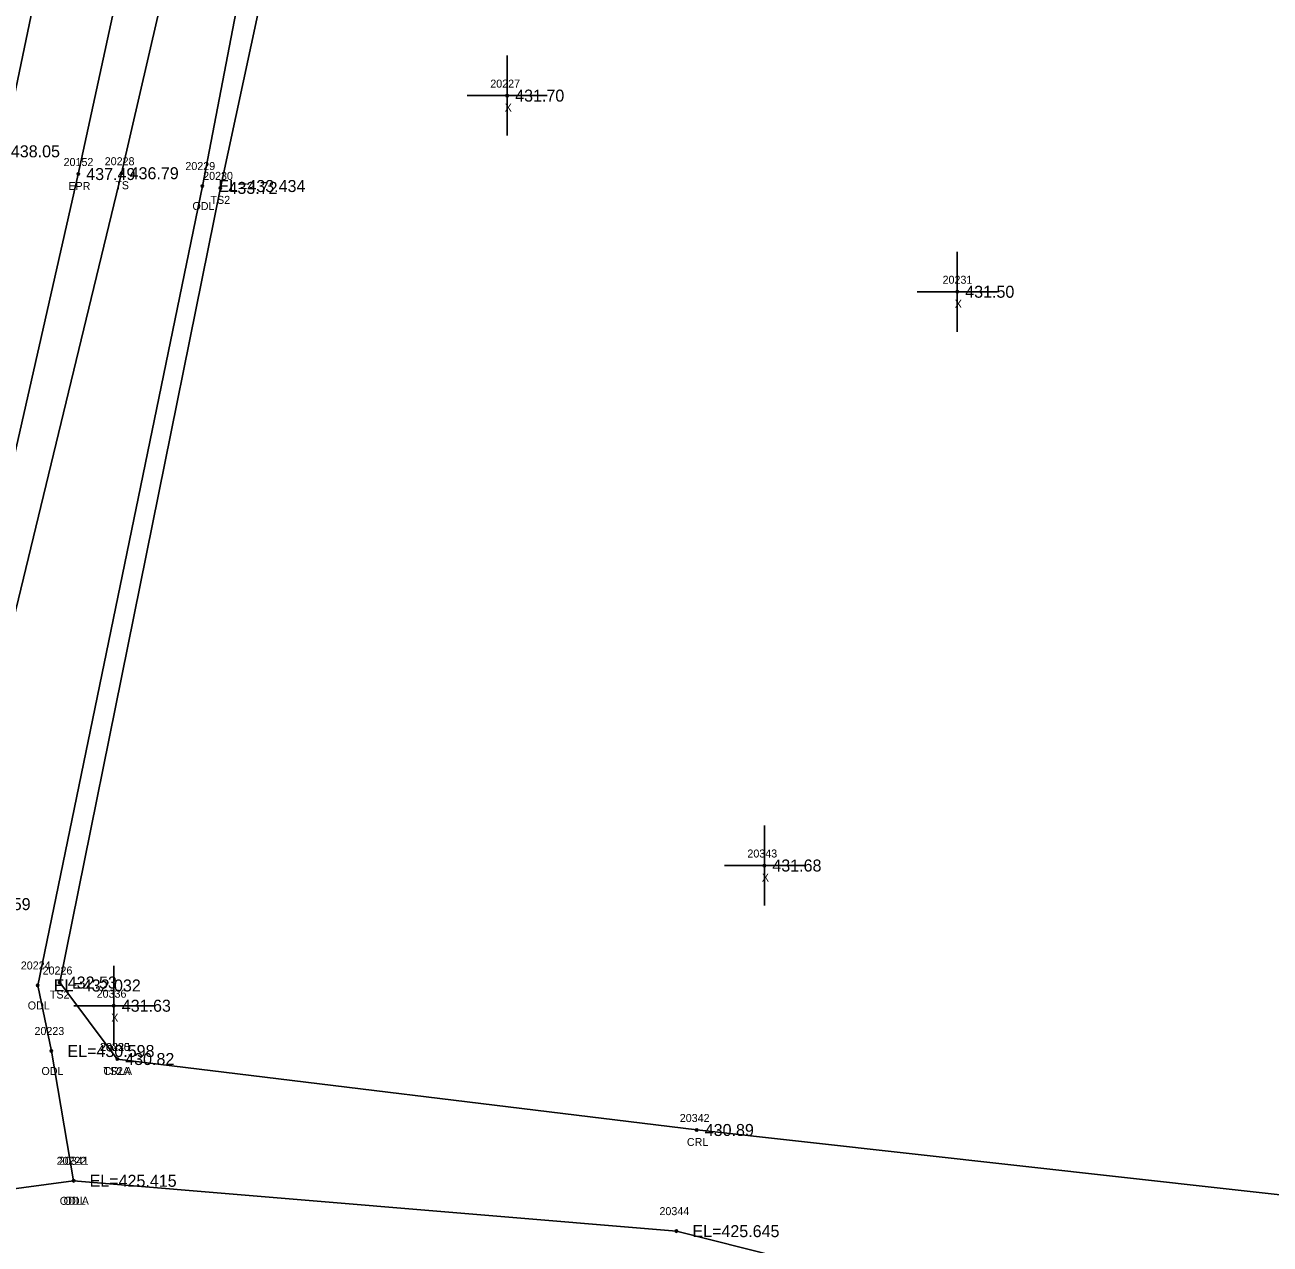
# Model space of a CAD drawing. Extents: x 1755707 to 1756750, y 975854 to 977363.
# Drawn here: x 1756236.1 to 1756391.7, y 976608 to 976760.4 of the extents above; entities that cross this region are included whole.
import ezdxf

# ---------------------------------------------------------------- set-up
doc = ezdxf.new("R2010")
doc.units = 0
for name, color, linetype in [('RD_DTM_BkLn1', 7, 'Continuous'), ('RD_DTM_BkLn2', 7, 'Continuous'), ('RD_DTM_BkLn_txCode', 7, 'Continuous'), ('RD_EX_H2O', 7, 'Continuous'), ('RD_EX_H2O_txCode', 7, 'Continuous'), ('RD_EX_Misc', 7, 'Continuous'), ('RD_EX_Misc_txCode', 7, 'Continuous'), ('RD_EX_Road', 7, 'Continuous'), ('RD_EX_Road_txCode', 7, 'Continuous'), ('RD_EX_TX_H2O_ELEV', 7, 'Continuous'), ('RD_EX_TX_Misc_ELEV', 7, 'Continuous'), ('RD_EX_TX_Road_ELEV', 7, 'Continuous'), ('RD_HC_Survey_ELEV', 7, 'Continuous'), ('RD_SMD_Locator', 7, 'Continuous')]:
    doc.layers.add(name, color=color, linetype=linetype)

msp = doc.modelspace()

# ---------------------------------------------------------------- linework, layer by layer
at = {"layer": 'RD_DTM_BkLn1'}
msp.add_lwpolyline([(1756212.24, 976646.92), (1756233.31, 976744.58), (1756253.87, 976843.36), (1756274.18, 976942.87), (1756294.7, 977044.28), (1756314.7, 977141.54), (1756335.65, 977241.96), (1756357.9, 977342.03)], dxfattribs=at)
at = {"layer": 'RD_DTM_BkLn2'}
for points in [[(1756228.43, 976635.42), (1756229.64, 976650.51), (1756228.61, 976661.27), (1756248.15, 976741.84), (1756270.72, 976839.45), (1756280.12, 976897.48), (1756286.17, 976899.18), (1756290.15, 976895.42)], [(1756247.6, 976631.15), (1756240.42, 976640.71), (1756260.5, 976740.01), (1756281.57, 976838.1), (1756290.15, 976895.42)]]:
    msp.add_lwpolyline(points, dxfattribs=at)
at = {"layer": 'RD_EX_H2O'}
for points in [[(1756242.15, 976615.93), (1756239.38, 976632.15), (1756237.67, 976640.34), (1756258.24, 976740.24), (1756277.14, 976838.38), (1756286.35, 976895.13)], [(1756247.6, 976631.15), (1756320.02, 976622.28), (1756426.93, 976610.4), (1756522.42, 976596.33), (1756612.51, 976536.45), (1756713.08, 976499.13)], [(1755742.06, 976428.66), (1755806.09, 976451.93), (1755887.6, 976439.2), (1755982.53, 976463.01), (1756033.69, 976542.66), (1756128.83, 976549.6), (1756169.54, 976582.49), (1756188.08, 976603.54), (1756206.03, 976613.84), (1756222.85, 976613.36), (1756242.15, 976615.93), (1756317.48, 976609.64), (1756394.89, 976590.11), (1756422.33, 976593.66), (1756518.23, 976582.93), (1756609.24, 976524.24), (1756704.51, 976490.62)]]:
    msp.add_lwpolyline(points, dxfattribs=at)
at = {"layer": 'RD_EX_Misc'}
for p, q in [((1756296.33, 976746.54), (1756296.33, 976756.54)), ((1756291.33, 976751.54), (1756301.33, 976751.54)), ((1756352.57, 976722.03), (1756352.57, 976732.03)), ((1756347.57, 976727.03), (1756357.57, 976727.03)), ((1756328.47, 976650.33), (1756328.47, 976660.33)), ((1756323.47, 976655.33), (1756333.47, 976655.33)), ((1756247.17, 976632.81), (1756247.17, 976642.81)), ((1756242.17, 976637.81), (1756252.17, 976637.81))]:
    msp.add_line(p, q, dxfattribs=at)
at = {"layer": 'RD_EX_Road'}
msp.add_lwpolyline([(1756212.24, 976646.92), (1756220.86, 976645.39), (1756242.73, 976741.74), (1756264.15, 976840.28), (1756284.31, 976940.54), (1756305.17, 977042.39), (1756325.03, 977140.07), (1756346.16, 977239.41), (1756368.47, 977341.2)], dxfattribs=at)
at = {"layer": 'RD_SMD_Locator'}
for centre in [(1756296.33, 976751.54), (1756242.73, 976741.74), (1756248.15, 976741.84), (1756258.24, 976740.24), (1756260.5, 976740.01), (1756352.57, 976727.03), (1756328.47, 976655.33), (1756237.67, 976640.34), (1756240.42, 976640.71), (1756247.17, 976637.81), (1756239.38, 976632.15), (1756247.6, 976631.15), (1756247.6, 976631.15), (1756320.02, 976622.28), (1756242.15, 976615.93), (1756242.15, 976615.93), (1756317.48, 976609.64)]:
    msp.add_circle(centre, 0.15, dxfattribs=at)

# ---------------------------------------------------------------- texts
at = {"layer": 'RD_DTM_BkLn_txCode'}
for s, p in [('20228', (1756246.04, 976742.84)), ('20230', (1756258.34, 976741.01)), ('TS', (1756247.36, 976739.84)), ('TS2', (1756259.26, 976738.01)), ('20226', (1756238.28, 976641.71)), ('TS2', (1756239.18, 976638.71)), ('20225', (1756245.48, 976632.15)), ('TS2A', (1756245.86, 976629.15))]:
    msp.add_text(s, height=1, dxfattribs=at).set_placement(p)
at = {"layer": 'RD_EX_H2O_txCode'}
for s, p in [('20229', (1756256.12, 976742.24)), ('ODL', (1756257, 976737.24)), ('20224', (1756235.55, 976642.34)), ('ODL', (1756236.42, 976637.34)), ('20223', (1756237.26, 976634.15)), ('20330', (1756245.44, 976632.15)), ('ODL', (1756238.13, 976629.15)), ('CRLA', (1756245.88, 976629.15)), ('20342', (1756317.9, 976623.28)), ('CRL', (1756318.79, 976620.28)), ('20222', (1756240.03, 976617.93)), ('20341', (1756240.31, 976617.93)), ('ODLA', (1756240.42, 976612.93)), ('ODL', (1756240.9, 976612.93)), ('20344', (1756315.36, 976611.64))]:
    msp.add_text(s, height=1, dxfattribs=at).set_placement(p)
at = {"layer": 'RD_EX_Misc_txCode'}
for s, p in [('20227', (1756294.22, 976752.54)), ('X', (1756296.02, 976749.54)), ('20231', (1756350.74, 976728.03)), ('X', (1756352.26, 976725.03)), ('20343', (1756326.35, 976656.33)), ('X', (1756328.16, 976653.33)), ('20336', (1756245.03, 976638.81)), ('X', (1756246.85, 976635.81))]:
    msp.add_text(s, height=1, dxfattribs=at).set_placement(p)
at = {"layer": 'RD_EX_Road_txCode'}
for s, p in [('20152', (1756240.9, 976742.74)), ('EPR', (1756241.5, 976739.74))]:
    msp.add_text(s, height=1, dxfattribs=at).set_placement(p)
at = {"layer": 'RD_EX_TX_H2O_ELEV'}
for s, p in [('EL=433.434', (1756260.24, 976739.49)), ('EL=432.032', (1756239.67, 976639.59)), ('EL=430.598', (1756241.38, 976631.4)), ('430.82', (1756248.6, 976630.4)), ('430.89', (1756321.02, 976621.53)), ('EL=425.415', (1756244.15, 976615.18)), ('EL=425.415', (1756244.15, 976615.18)), ('EL=425.645', (1756319.48, 976608.89))]:
    msp.add_text(s, height=1.5, dxfattribs=at).set_placement(p)
at = {"layer": 'RD_EX_TX_Misc_ELEV'}
for s, p in [('431.70', (1756297.33, 976750.79)), ('436.79', (1756249.15, 976741.09)), ('433.72', (1756261.5, 976739.26)), ('431.50', (1756353.57, 976726.28)), ('431.68', (1756329.47, 976654.58)), ('436.59', (1756230.64, 976649.76)), ('432.53', (1756241.42, 976639.96)), ('431.63', (1756248.17, 976637.06)), ('430.82', (1756248.6, 976630.4))]:
    msp.add_text(s, height=1.5, dxfattribs=at).set_placement(p)
at = {"layer": 'RD_EX_TX_Road_ELEV'}
msp.add_text('437.49', height=1.5, dxfattribs=at).set_placement((1756243.73, 976740.99))
at = {"layer": 'RD_HC_Survey_ELEV'}
msp.add_text('438.05', height=1.5, dxfattribs=at).set_placement((1756234.31, 976743.83))

doc.saveas('drawing.dxf')
